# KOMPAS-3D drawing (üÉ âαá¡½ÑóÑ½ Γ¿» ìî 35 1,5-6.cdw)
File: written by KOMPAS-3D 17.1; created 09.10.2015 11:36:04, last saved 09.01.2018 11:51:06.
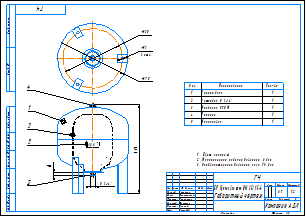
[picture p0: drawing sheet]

Sheet 1: A3, landscape

Title block, sheet 1: name: БР Гранлевел тип НМ 35/1,5-6 / Габаритный чертеж; mass: 6.1; scale: 1:2; sheets: 1; organisation: Компания АДЛ; cell 10: Нач.отд.; sheet format: A3; stored path: \\Fsk1.adlc.lan\files\АП\20_PKO\02_Насосное направление\АУПД\Чертежи на баки\Чертеж.cdw; drawn by: Лощинин; checked by: Хантимеров; technical control: Курлыкина; cell 113: Щетинин; standards control: Долгов; approved by: Рашидов

Views: Вид 3, Спереди, Проекционный вид 4
Referenced files in \\Fsk1\FILES\АП\20_PKO\02_Насосное направление\Разработка\04_Проекты разные\Баки\КД действующая\flexcon r_dwg\Компас\: 35 литров.a3d, 8 литров.a3d
Referenced files in \\Fsk1\files\АП\20_PKO\02_Насосное направление\Разработка\04_Проекты разные\Баки\КД действующая\Баки Flexcon R\Компас\: 35 литров.a3d
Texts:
  ADL
  romans
  romand
  romant
  АДЛ
  TRAZO_Y_PUNTOX2_RGB_0_255_0_SC_2_THICK_0.05
  TRAZO_Y_PUNTOX2_RGB_0_255_0_SC_1_THICK_0.05
  TRAZO_Y_PUNTOX2_RGB_0_255_0_SC_0.3_THICK_0.05
  POLYLINE_STYLE_0.30_RGB_0_0_0
  ACAD_ISO03W100_RGB_223_127_255_SC_0.5_THICK_0.05
  ACAD_ISO03W100_RGB_223_127_255_SC_1_THICK_0.05
  TRAZO_Y_PUNTOX2_RGB_0_255_0_SC_0.25_THICK_0.05
  СONTINUOUS_RGB_223_127_255_THICK_0.05
  ACAD_ISO03W100_RGB_223_127_255_SC_0.25_THICK_0.05
  TRAZO_Y_PUNTOX2_RGB_0_255_0_SC_3_THICK_0.05
  POLYLINE_STYLE_0.35_RGB_0_0_0
  TRAZO_Y_PUNTOX2_RGB_0_255_0_SC_0.5_THICK_0.05
  TRAZO_Y_PUNTOX2_RGB_0_255_0_SC_0.4_THICK_0.05
  ACAD_ISO03W100_RGB_223_127_255_SC_0.046_THICK_0.05
  ACAD_ISO03W100_RGB_223_127_255_SC_0.24_THICK_0.05
  ACAD_ISO03W100_RGB_223_127_255_SC_0.15_THICK_0.05
  ACAD_ISO03W100_RGB_223_127_255_SC_0.0081_THICK_0.05
  ACAD_ISO03W100_RGB_223_127_255_SC_0.0092_THICK_0.05
  ACAD_ISO03W100_RGB_223_127_255_SC_0.14_THICK_0.05
  ACAD_ISO03W100_RGB_223_127_255_SC_0.16_THICK_0.05
  ACAD_ISO03W100_RGB_223_127_255_SC_0.31_THICK_0.05
  ACAD_ISO03W100_RGB_223_127_255_SC_0.47_THICK_0.05
  ACAD_ISO03W100_RGB_223_127_255_SC_0.26_THICK_0.05
  ACAD_ISO03W100_RGB_223_127_255_SC_0.36_THICK_0.05
  CONTINUOUS_RGB_0_0_0_THICK_0.3
  ACAD_ISO03W100_RGB_223_127_255_SC_0.027_THICK_0.05
  ACAD_ISO03W100_RGB_223_127_255_SC_0.18_THICK_0.05
  ACAD_ISO03W100_RGB_223_127_255_SC_0.4_THICK_0.05
  ACAD_ISO03W100_RGB_223_127_255_SC_0.016_THICK_0.05
  ACAD_ISO03W100_RGB_223_127_255_SC_0.057_THICK_0.05
  ACAD_ISO03W100_RGB_223_127_255_SC_0.23_THICK_0.05
  ACAD_ISO03W100_RGB_223_127_255_SC_0.011_THICK_0.05
  ACAD_ISO03W100_RGB_223_127_255_SC_0.42_THICK_0.05
  ACAD_ISO03W100_RGB_223_127_255_SC_0.29_THICK_0.05
  ACAD_ISO03W100_RGB_223_127_255_SC_0.061_THICK_0.05
  ACAD_ISO03W100_RGB_223_127_255_SC_0.32_THICK_0.05
  ACAD_ISO03W100_RGB_223_127_255_SC_0.002_THICK_0.05
  ACAD_ISO03W100_RGB_223_127_255_SC_0.065_THICK_0.05
  ACAD_ISO03W100_RGB_223_127_255_SC_0.28_THICK_0.05
  ACAD_ISO03W100_RGB_223_127_255_SC_0.058_THICK_0.05
  ACAD_ISO03W100_RGB_223_127_255_SC_0.022_THICK_0.05
  ACAD_ISO03W100_RGB_223_127_255_SC_0.0055_THICK_0.05
  ACAD_ISO03W100_RGB_223_127_255_SC_0.19_THICK_0.05
  ACAD_ISO03W100_RGB_223_127_255_SC_0.22_THICK_0.05
  ACAD_ISO03W100_RGB_223_127_255_SC_0.12_THICK_0.05
  ACAD_ISO03W100_RGB_223_127_255_SC_0.21_THICK_0.05
  ACAD_ISO03W100_RGB_223_127_255_SC_0.1_THICK_0.05
  CONTINUOUS_RGB_255_223_127_THICK_0.15
  ACAD_ISO03W100_RGB_223_127_255_SC_0.085_THICK_0.05
  ACAD_ISO03W100_RGB_223_127_255_SC_0.026_THICK_0.05
  ACAD_ISO03W100_RGB_223_127_255_SC_0.05_THICK_0.05
  ACAD_ISO03W100_RGB_223_127_255_SC_0.3_THICK_0.05
  ACAD_ISO03W100_RGB_223_127_255_SC_0.33_THICK_0.05
  ACAD_ISO03W100_RGB_223_127_255_SC_0.49_THICK_0.05
  ACAD_ISO03W100_RGB_223_127_255_SC_0.37_THICK_0.05
  ACAD_ISO03W100_RGB_223_127_255_SC_0.035_THICK_0.05
  ACAD_ISO03W100_RGB_223_127_255_SC_0.018_THICK_0.05
  ACAD_ISO03W100_RGB_223_127_255_SC_0.45_THICK_0.05
  ACAD_ISO03W100_RGB_223_127_255_SC_0.051_THICK_0.05
  CONTINUOUS_RGB_255_0_0_THICK_0.05
  CONTINUOUS_RGB_255_191_0_THICK_0.05
  TRAZO_Y_PUNTOX2_RGB_0_255_0_SC_0.13_THICK_0.05
  CONTINUOUS_RGB_191_255_127_THICK_0.05
  ACAD_ISO03W100_RGB_223_127_255_SC_0.042_THICK_0.05
  ACAD_ISO03W100_RGB_223_127_255_SC_0.27_THICK_0.05
  ACAD_ISO03W100_RGB_223_127_255_SC_0.0016_THICK_0.05
  ACAD_ISO03W100_RGB_223_127_255_SC_0.099_THICK_0.05
  ACAD_ISO03W100_RGB_223_127_255_SC_0.0058_THICK_0.05
  ACAD_ISO03W100_RGB_223_127_255_SC_0.0074_THICK_0.05
  ACAD_ISO03W100_RGB_223_127_255_SC_0.088_THICK_0.05
  ACAD_ISO03W100_RGB_223_127_255_SC_0.0023_THICK_0.05
  ACAD_ISO03W100_RGB_223_127_255_SC_0.38_THICK_0.05
  ACAD_ISO03W100_RGB_223_127_255_SC_0.093_THICK_0.05
  ACAD_ISO03W100_RGB_223_127_255_SC_0.34_THICK_0.05
  ACAD_ISO03W100_RGB_223_127_255_SC_0.087_THICK_0.05
  ACAD_ISO03W100_RGB_223_127_255_SC_0.015_THICK_0.05
  ACAD_ISO03W100_RGB_223_127_255_SC_0.2_THICK_0.05
  ACAD_ISO03W100_RGB_223_127_255_SC_0.41_THICK_0.05
  ACAD_ISO03W100_RGB_223_127_255_SC_0.35_THICK_0.05
  ACAD_ISO03W100_RGB_223_127_255_SC_0.0006_THICK_0.05
  ACAD_ISO03W100_RGB_223_127_255_SC_0.012_THICK_0.05
  CONTINUOUS_RGB_255_223_127_THICK_0.05
  TRAZO_Y_PUNTOX2_RGB_0_255_0_SC_0.35_THICK_0.05
  TRAZO_Y_PUNTOX2_RGB_0_255_0_SC_0.2_THICK_0.05
  TRAZO_Y_PUNTOX2_RGB_0_255_0_SC_0.08_THICK_0.05
  ACAD_ISO03W100_RGB_223_127_255_SC_0.8_THICK_0.05
  TRAZO_Y_PUNTOX2_RGB_0_255_0_SC_0.75_THICK_0.05
  ACAD_ISO03W100_RGB_223_127_255_SC_0.13_THICK_0.05
  ACAD_ISO03W100_RGB_223_127_255_SC_0.063_THICK_0.05
  TRAZO_Y_PUNTOX2_RGB_0_255_0_SC_0.11_THICK_0.05
  HOUND_ISO 0
  HOUND_ISO 1
  ANGLE_ISO 0
  ANGLE_ISO 1
  AR-CONC_ISO
  AR-CONC_ISO 0
  AR-CONC_ISO 1
  AR-CONC_ISO 2
  AR-CONC_ISO 3
  AR-CONC_ISO 4
  AR-CONC_ISO 5
  AR-CONC_ISO 6
  AR-CONC_ISO 7
  AR-CONC_ISO 8
  AR-CONC_ISO 9
  AR-CONC_ISO 10
  AR-CONC_ISO 11
  AR-CONC_ISO 12
  ANSI38_ISO 1
Dimensions and other numbers on the sheet: 496; 16; 330; 390; 13; 3 отв.; 1:2; 1; 6.1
